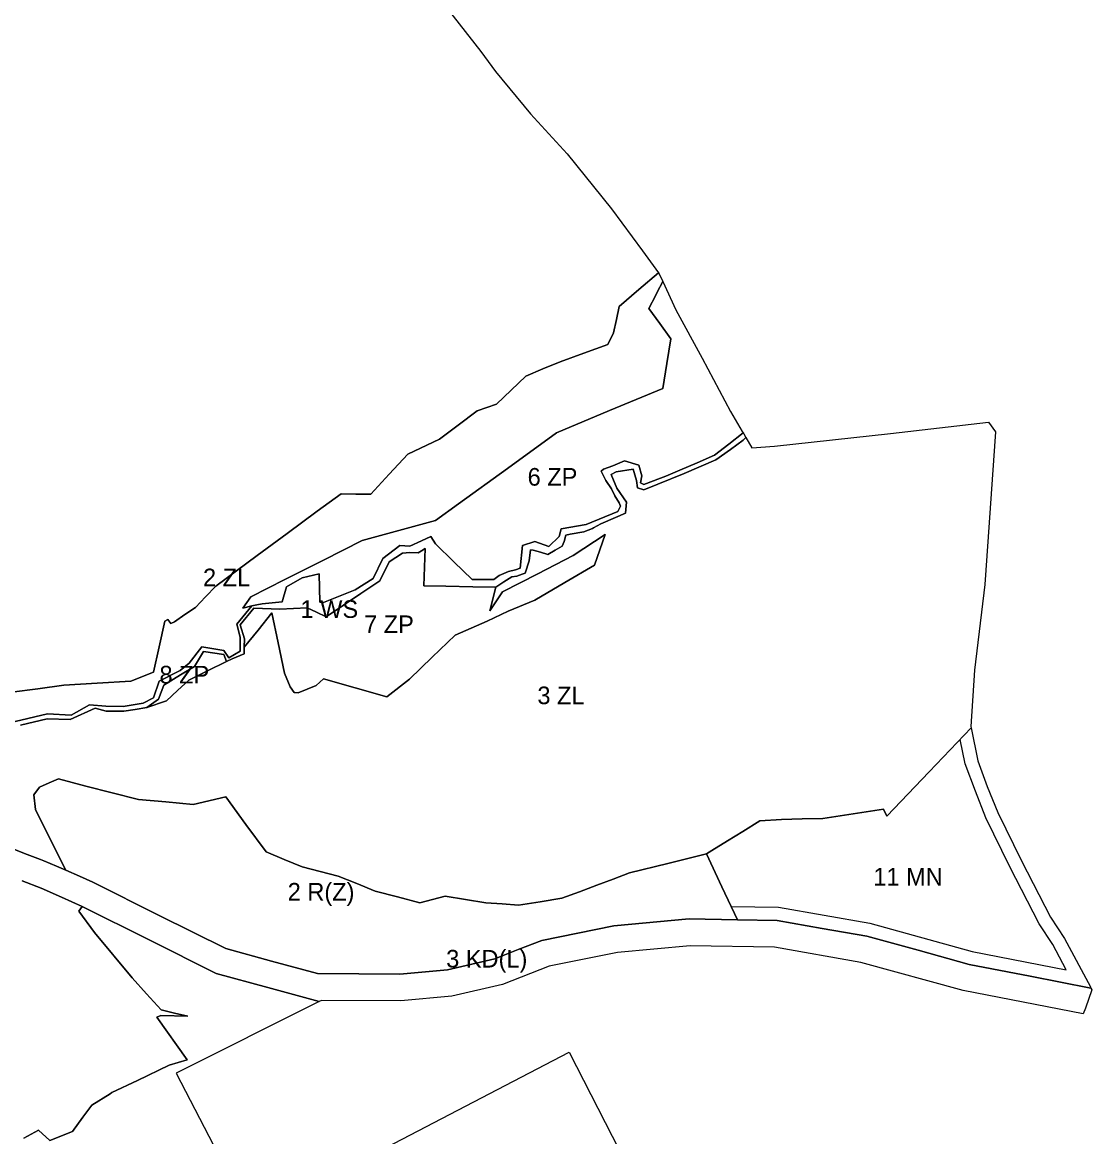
# Model space of a CAD drawing. Extents: x 7423691 to 7425475, y 5552085 to 5554331.
# Drawn here: x 7424989 to 7425475, y 5552921 to 5553427 of the extents above; entities that cross this region are included whole.
import ezdxf

# ---------------------------------------------------------------- set-up
doc = ezdxf.new("R2010")
doc.units = 0
for name, color, linetype in [('linia_zabudowy_nieprzekraczalna', 7, 'Continuous'), ('linie_rozgraniczajace', 7, 'Continuous'), ('oznaczenia_przeznaczen', 7, 'Continuous')]:
    doc.layers.add(name, color=color, linetype=linetype)

msp = doc.modelspace()

# ---------------------------------------------------------------- linework, layer by layer
at = {"layer": 'linia_zabudowy_nieprzekraczalna'}
msp.add_lwpolyline([(7425310.98, 5553025.96), (7425332.48, 5553025.57), (7425373.87, 5553018.32), (7425420.41, 5553005.53), (7425463, 5552997.24), (7425456.94, 5553008.72), (7425450.74, 5553018.12), (7425437.39, 5553044), (7425426.59, 5553066.12), (7425421.88, 5553078.25), (7425417.12, 5553090.67), (7425414.88, 5553101.71)], dxfattribs=at)
at = {"layer": 'linie_rozgraniczajace'}
for points in [[(7425174.89, 5553442.76), (7425197.38, 5553414.04), (7425204.01, 5553404.96), (7425219.92, 5553385.71), (7425236.54, 5553367.58), (7425256.65, 5553342.51), (7425270.66, 5553323.46), (7425277.93, 5553313.56), (7425269.08, 5553305.92), (7425260.22, 5553298.28), (7425258.9, 5553292.27), (7425257.58, 5553286.26), (7425254.94, 5553280.93), (7425244.14, 5553277.04), (7425233.34, 5553273.16), (7425225.57, 5553269.89), (7425217.8, 5553266.62), (7425211.12, 5553260.26), (7425204.44, 5553253.9), (7425195.62, 5553250.91), (7425187.09, 5553244.43), (7425178.55, 5553237.96), (7425164.26, 5553231.17)], [(7424984.37, 5553123.2), (7424996.23, 5553124.78), (7425008.08, 5553126.36), (7425023.27, 5553127.31), (7425038.45, 5553128.25), (7425048.85, 5553132.27), (7425051.36, 5553143.84), (7425053.88, 5553155.41), (7425055.33, 5553156.21), (7425056.71, 5553154.45), (7425058.28, 5553155.19), (7425063.03, 5553158.4), (7425067.78, 5553161.6), (7425072.42, 5553166.44), (7425077.07, 5553171.27), (7425086.44, 5553178.22), (7425095.81, 5553185.18), (7425109.45, 5553195.25), (7425123.08, 5553205.31), (7425128.53, 5553209.28), (7425133.97, 5553213.25), (7425140.68, 5553213.12), (7425147.39, 5553213), (7425155.82, 5553222.08), (7425164.26, 5553231.17), (7425178.55, 5553237.96), (7425187.09, 5553244.43), (7425195.62, 5553250.91), (7425204.44, 5553253.9), (7425211.12, 5553260.26), (7425217.8, 5553266.62), (7425225.57, 5553269.89), (7425233.34, 5553273.16), (7425244.14, 5553277.04), (7425254.94, 5553280.93), (7425257.58, 5553286.26), (7425258.9, 5553292.27), (7425260.22, 5553298.28), (7425269.08, 5553305.92), (7425277.93, 5553313.56), (7425278.32, 5553313.03), (7425279.89, 5553309.63), (7425277.38, 5553304.74), (7425276.73, 5553303.46), (7425273.56, 5553297.29), (7425278.56, 5553290.46), (7425283.57, 5553283.62), (7425281.77, 5553272.35), (7425279.96, 5553261.09), (7425255.82, 5553251), (7425231.68, 5553240.91), (7425209.42, 5553224.79), (7425187.17, 5553208.66), (7425176.76, 5553201.13), (7425160.1, 5553196.59), (7425143.45, 5553192.06), (7425125.91, 5553183.17), (7425108.38, 5553174.29), (7425092.89, 5553166.43), (7425089.31, 5553161.33), (7425093.37, 5553162.39), (7425086.56, 5553154.02), (7425088.12, 5553148.21), (7425088.15, 5553141.83), (7425082.9, 5553138.78), (7425080.71, 5553142.05), (7425070.77, 5553143.82), (7425064.97, 5553136.39), (7425060.96, 5553133.03), (7425051.34, 5553128.27), (7425048.78, 5553120.71), (7425044.11, 5553118.21), (7425035, 5553116.67), (7425027.17, 5553116.83), (7425019.66, 5553117.44), (7425011.4, 5553112.71), (7425000.71, 5553113.41), (7424985.93, 5553109.97)], [(7424988.39, 5553108.24), (7425000.54, 5553111.18), (7425010.99, 5553110.87), (7425022.24, 5553115.95), (7425027.23, 5553114.59), (7425035.27, 5553114.53), (7425040.53, 5553115.41), (7425045.8, 5553116.29), (7425054.68, 5553119.32), (7425059.73, 5553124.03), (7425064.78, 5553128.73), (7425073.35, 5553132.97), (7425081.91, 5553137.2), (7425084.55, 5553138.33), (7425089.94, 5553140.64), (7425089.91, 5553143.58), (7425096.24, 5553151.4), (7425102.56, 5553159.23), (7425105.38, 5553145.55), (7425108.19, 5553131.87), (7425110.76, 5553125.58), (7425112.63, 5553123.06), (7425114.45, 5553122.93), (7425122.55, 5553126.23), (7425125.96, 5553129.2), (7425140.29, 5553125.17), (7425154.62, 5553121.14), (7425164.96, 5553129.05), (7425175.31, 5553139.07), (7425185.67, 5553149.08), (7425200.17, 5553155.46), (7425209.83, 5553159.92), (7425221.85, 5553165.01), (7425235.41, 5553172.91), (7425248.97, 5553180.82), (7425253.74, 5553194.8), (7425239.2, 5553185.23), (7425223.21, 5553176.96), (7425207.23, 5553168.69), (7425201.4, 5553160.13), (7425204.23, 5553170.93), (7425207.84, 5553173.26), (7425211.44, 5553175.59), (7425213.67, 5553175.81), (7425216.08, 5553176.79), (7425217.47, 5553177.18), (7425219.33, 5553182.8), (7425219.86, 5553187.81), (7425221.06, 5553187.67), (7425224.42, 5553186.71), (7425227.79, 5553185.75), (7425231.05, 5553187.62), (7425234.31, 5553189.49), (7425235.16, 5553191.52), (7425235.95, 5553194.4), (7425237.92, 5553194.93), (7425244.14, 5553195.92), (7425247.99, 5553197.55), (7425248.44, 5553197.79), (7425251.86, 5553199.56), (7425258.5, 5553202.49), (7425263, 5553204.41), (7425263.5, 5553209.42), (7425259.04, 5553215.78), (7425256.55, 5553221.93), (7425258.75, 5553223.2), (7425266.52, 5553224.47), (7425268.06, 5553219.27), (7425268.46, 5553216.02), (7425271.27, 5553215.05), (7425277.72, 5553217.62), (7425289.6, 5553222.52), (7425304.07, 5553228.69), (7425310.64, 5553233.41), (7425316.37, 5553237.52), (7425317.62, 5553238.81), (7425320.37, 5553234.15), (7425330.64, 5553234.89), (7425383.28, 5553240.6), (7425427.73, 5553245.73), (7425430.92, 5553241.36), (7425426.1, 5553172.1), (7425421.47, 5553133.23), (7425419.8, 5553107.66), (7425419.94, 5553106.99), (7425400.8, 5553086.99), (7425381.66, 5553066.98), (7425380.1, 5553070.04)], [(7424985.93, 5553109.97), (7425000.71, 5553113.41), (7425011.4, 5553112.71), (7425019.66, 5553117.44), (7425027.17, 5553116.83), (7425035, 5553116.67), (7425044.11, 5553118.21), (7425048.78, 5553120.71), (7425051.34, 5553128.27), (7425060.96, 5553133.03), (7425064.97, 5553136.39), (7425070.77, 5553143.82), (7425080.71, 5553142.05), (7425082.9, 5553138.78), (7425088.15, 5553141.83), (7425088.12, 5553148.21), (7425086.56, 5553154.02), (7425093.37, 5553162.39), (7425095.72, 5553162.82), (7425098.07, 5553163.25), (7425107.12, 5553164.19), (7425109.09, 5553171.06), (7425116.25, 5553175.14), (7425124.05, 5553176.91), (7425124.31, 5553164.11), (7425125.97, 5553163.97), (7425140.27, 5553169.67), (7425148.44, 5553174.82), (7425152.85, 5553183.92), (7425160.63, 5553189.75), (7425165.17, 5553189.47), (7425170.45, 5553191.96), (7425174.64, 5553193.85), (7425176.75, 5553190.53), (7425185.05, 5553182.42), (7425193.35, 5553174.31), (7425203.26, 5553174.42), (7425205.67, 5553176.11), (7425209.97, 5553177.99), (7425213.1, 5553178.7), (7425215.22, 5553179.43), (7425216.2, 5553189.74), (7425221.81, 5553191.55), (7425228.25, 5553189.38), (7425232.93, 5553193.9), (7425233.88, 5553197.36), (7425245.18, 5553199.33), (7425259.6, 5553205.21), (7425260.69, 5553207.59), (7425260.13, 5553209.15), (7425258.25, 5553212.35), (7425256.66, 5553215.52), (7425254.03, 5553219.21), (7425252.03, 5553223.45), (7425252.99, 5553224.39), (7425257.22, 5553225.87), (7425262.59, 5553228.13), (7425269, 5553226.28), (7425270.5, 5553221.4), (7425269.79, 5553218.18), (7425271.4, 5553217.43), (7425278.9, 5553220.26), (7425281.4, 5553221.24), (7425283.48, 5553222.17), (7425287.7, 5553223.94), (7425295.49, 5553227.27), (7425303.45, 5553230.75), (7425309.91, 5553235.84), (7425316.37, 5553240.93), (7425316.67, 5553240.43), (7425317.62, 5553238.81), (7425316.37, 5553237.52), (7425310.64, 5553233.41), (7425304.07, 5553228.69), (7425289.6, 5553222.52), (7425277.72, 5553217.62), (7425271.27, 5553215.05), (7425268.46, 5553216.02), (7425268.06, 5553219.27), (7425266.52, 5553224.47), (7425258.75, 5553223.2), (7425256.55, 5553221.93), (7425259.04, 5553215.78), (7425263.5, 5553209.42), (7425263, 5553204.41), (7425258.5, 5553202.49), (7425251.86, 5553199.56), (7425248.44, 5553197.79), (7425247.99, 5553197.55), (7425244.14, 5553195.92)], [(7425164.26, 5553231.17), (7425155.82, 5553222.08), (7425147.39, 5553213), (7425140.68, 5553213.12), (7425133.97, 5553213.25), (7425128.53, 5553209.28), (7425123.08, 5553205.31), (7425109.45, 5553195.25), (7425095.81, 5553185.18), (7425086.44, 5553178.22), (7425077.07, 5553171.27), (7425072.42, 5553166.44), (7425067.78, 5553161.6), (7425063.03, 5553158.4), (7425058.28, 5553155.19), (7425056.71, 5553154.45), (7425055.33, 5553156.21), (7425053.88, 5553155.41), (7425051.36, 5553143.84), (7425048.85, 5553132.27), (7425038.45, 5553128.25), (7425023.27, 5553127.31), (7425008.08, 5553126.36), (7424996.23, 5553124.78), (7424984.37, 5553123.2)], [(7425244.14, 5553195.92), (7425237.92, 5553194.93), (7425235.95, 5553194.4), (7425235.16, 5553191.52), (7425234.31, 5553189.49), (7425231.05, 5553187.62), (7425227.79, 5553185.75), (7425224.42, 5553186.71), (7425221.06, 5553187.67), (7425219.86, 5553187.81), (7425219.33, 5553182.8), (7425217.47, 5553177.18), (7425216.08, 5553176.79), (7425213.67, 5553175.81), (7425211.44, 5553175.59), (7425207.84, 5553173.26), (7425204.23, 5553170.93), (7425193.78, 5553171.06), (7425181.4, 5553171.32), (7425171.42, 5553171.53), (7425172.15, 5553188.39), (7425170.43, 5553187.39), (7425168.87, 5553186.48), (7425165.13, 5553186.57), (7425161.74, 5553186.29), (7425155.79, 5553182.36), (7425151.58, 5553173.75), (7425142.94, 5553167.94), (7425135.03, 5553162.66), (7425127.12, 5553157.38), (7425122.81, 5553159.47), (7425118.5, 5553161.56), (7425106.06, 5553160.88), (7425094.29, 5553161.31), (7425088.1, 5553153.82), (7425090.16, 5553147.36), (7425089.91, 5553143.59), (7425089.91, 5553143.58), (7425089.94, 5553140.64), (7425084.55, 5553138.33), (7425081.91, 5553137.2), (7425080.72, 5553140.28), (7425071.43, 5553141.66), (7425067.34, 5553134.92), (7425061.07, 5553131.07), (7425053.45, 5553126.4), (7425051.07, 5553119.97), (7425045.8, 5553116.29), (7425040.53, 5553115.41), (7425035.27, 5553114.53), (7425027.23, 5553114.59), (7425022.24, 5553115.95), (7425010.99, 5553110.87), (7425000.54, 5553111.18), (7424988.39, 5553108.24)], [(7425380.1, 5553070.04), (7425374.17, 5553069.15), (7425360.43, 5553067.11), (7425352.62, 5553065.94), (7425343.19, 5553065.66), (7425333.77, 5553065.37), (7425323.95, 5553064.79), (7425316.29, 5553060.05), (7425309.29, 5553055.71), (7425302.28, 5553051.37), (7425299.71, 5553049.79), (7425282.27, 5553045.49), (7425264.83, 5553041.19), (7425257.42, 5553038.42), (7425250.01, 5553035.64), (7425242.1, 5553032.65), (7425234.19, 5553029.66), (7425224.31, 5553028.13), (7425214.43, 5553026.6), (7425207.01, 5553027.13), (7425199.59, 5553027.67), (7425190.38, 5553029.13), (7425181.16, 5553030.58), (7425175.38, 5553029.1), (7425169.6, 5553027.62), (7425159.53, 5553030.28), (7425149.45, 5553032.93), (7425141.04, 5553036.33), (7425132.63, 5553039.73), (7425124.44, 5553041.86), (7425116.25, 5553043.98), (7425108.08, 5553047.33), (7425099.91, 5553050.69), (7425090.73, 5553063.17), (7425081.55, 5553075.65), (7425066.77, 5553072.25), (7425054.37, 5553073.38), (7425041.97, 5553074.51), (7425030.06, 5553077.54), (7425018.14, 5553080.57), (7425005.69, 5553083.89), (7425001.36, 5553082), (7424997.02, 5553080.11), (7424994.52, 5553076.63), (7424995.15, 5553069.94), (7425002.1, 5553056.18), (7425009.04, 5553042.42), (7425004.82, 5553044.3), (7424998.98, 5553046.7), (7424997.44, 5553047.3), (7424991.49, 5553049.58), (7424984.92, 5553052.11)], [(7424984.92, 5553052.11), (7424991.49, 5553049.58), (7424997.44, 5553047.3), (7424998.98, 5553046.7), (7425004.82, 5553044.3), (7425009.04, 5553042.42), (7425015.15, 5553039.68), (7425021.25, 5553036.95), (7425051.39, 5553021.89), (7425081.54, 5553006.84), (7425102.39, 5553001.17), (7425123.24, 5552995.5), (7425141.91, 5552995.38), (7425160.59, 5552995.27), (7425182.3, 5552997.2), (7425203.66, 5553002.25), (7425214.32, 5553006.37), (7425224.98, 5553010.5), (7425241.34, 5553013.83), (7425257.7, 5553017.16), (7425291.97, 5553020.3), (7425313.84, 5553019.91), (7425331.91, 5553019.58), (7425352.23, 5553016.02), (7425372.55, 5553012.46), (7425395.8, 5553006.07), (7425419.04, 5552999.68), (7425446.66, 5552994.31), (7425474.29, 5552988.93), (7425474.63, 5552988.05), (7425471.74, 5552979.82), (7425470.77, 5552977.23), (7425416.24, 5552987.84), (7425369.87, 5553000.59), (7425330.7, 5553007.45), (7425292.36, 5553008.14), (7425259.4, 5553005.12), (7425228.31, 5552998.79), (7425207.16, 5552990.61), (7425184.17, 5552985.18), (7425161.03, 5552983.11), (7425125.03, 5552983.34), (7425124.05, 5552982.85), (7425100.64, 5552989.21), (7425077.24, 5552995.57), (7425046.79, 5553010.78), (7425016.35, 5553026), (7425007.05, 5553030.16), (7424997.75, 5553034.32), (7424989.1, 5553037.64)], [(7424989.1, 5553037.64), (7424997.75, 5553034.32), (7425007.05, 5553030.16), (7425016.35, 5553026), (7425014.91, 5553023.77), (7425022.01, 5553014.15), (7425039.11, 5552993.64), (7425045.66, 5552986.35), (7425052.21, 5552979.06), (7425058.27, 5552977.58), (7425064.33, 5552976.1), (7425052.17, 5552976.42), (7425050.24, 5552975.78), (7425064, 5552956.38), (7425055.95, 5552953.87), (7425041.5, 5552946.99), (7425029.93, 5552941.48), (7425029.07, 5552940.94), (7425020.72, 5552935.8), (7425016.76, 5552930.36), (7425011.96, 5552923.77), (7425001.77, 5552919.8), (7424996.57, 5552924.37), (7424989.86, 5552920.81)], [(7424989.86, 5552920.81), (7424996.57, 5552924.37), (7425001.77, 5552919.8), (7425011.96, 5552923.77), (7425016.76, 5552930.36), (7425020.72, 5552935.8), (7425029.07, 5552940.94), (7425029.93, 5552941.48), (7425041.5, 5552946.99), (7425055.95, 5552953.87), (7425064, 5552956.38), (7425050.24, 5552975.78), (7425052.17, 5552976.42), (7425064.33, 5552976.1), (7425058.27, 5552977.58), (7425052.21, 5552979.06), (7425045.66, 5552986.35), (7425039.11, 5552993.64), (7425022.01, 5553014.15), (7425014.91, 5553023.77), (7425016.35, 5553026), (7425046.79, 5553010.78), (7425077.24, 5552995.57), (7425100.64, 5552989.21), (7425124.05, 5552982.85), (7425059.04, 5552950.27), (7425093.05, 5552884.67), (7425237.44, 5552959.76), (7425273.37, 5552889.73)]]:
    msp.add_lwpolyline(points, dxfattribs=at)
for points in [[(7425089.31, 5553161.33), (7425092.89, 5553166.43), (7425108.38, 5553174.29), (7425125.91, 5553183.17), (7425143.45, 5553192.06), (7425160.1, 5553196.59), (7425176.76, 5553201.13), (7425187.17, 5553208.66), (7425209.42, 5553224.79), (7425231.68, 5553240.91), (7425255.82, 5553251), (7425279.96, 5553261.09), (7425281.77, 5553272.35), (7425283.57, 5553283.62), (7425278.56, 5553290.46), (7425273.56, 5553297.29), (7425276.73, 5553303.46), (7425277.38, 5553304.74), (7425279.89, 5553309.63), (7425285.89, 5553296.68), (7425297.84, 5553274.81), (7425310.71, 5553250.62), (7425316.01, 5553241.54), (7425316.37, 5553240.93), (7425309.91, 5553235.84), (7425303.45, 5553230.75), (7425295.49, 5553227.27), (7425287.7, 5553223.94), (7425283.48, 5553222.17), (7425281.4, 5553221.24), (7425278.9, 5553220.26), (7425271.4, 5553217.43), (7425269.79, 5553218.18), (7425270.5, 5553221.4), (7425269, 5553226.28), (7425262.59, 5553228.13), (7425257.22, 5553225.87), (7425252.99, 5553224.39), (7425252.03, 5553223.45), (7425254.03, 5553219.21), (7425256.66, 5553215.52), (7425258.25, 5553212.35), (7425260.13, 5553209.15), (7425260.69, 5553207.59), (7425259.6, 5553205.21), (7425245.18, 5553199.33), (7425233.88, 5553197.36), (7425232.93, 5553193.9), (7425228.25, 5553189.38), (7425221.81, 5553191.55), (7425216.2, 5553189.74), (7425215.22, 5553179.43), (7425213.1, 5553178.7), (7425209.97, 5553177.99), (7425205.67, 5553176.11), (7425203.26, 5553174.42), (7425193.35, 5553174.31), (7425185.05, 5553182.42), (7425176.75, 5553190.53), (7425174.64, 5553193.85), (7425170.45, 5553191.96), (7425165.17, 5553189.47), (7425160.63, 5553189.75), (7425152.85, 5553183.92), (7425148.44, 5553174.82), (7425140.27, 5553169.67), (7425125.97, 5553163.97), (7425124.31, 5553164.11), (7425124.05, 5553176.91), (7425116.25, 5553175.14), (7425109.09, 5553171.06), (7425107.12, 5553164.19), (7425098.07, 5553163.25), (7425095.72, 5553162.82), (7425093.37, 5553162.39)], [(7425088.1, 5553153.82), (7425094.29, 5553161.31), (7425106.06, 5553160.88), (7425118.5, 5553161.56), (7425122.81, 5553159.47), (7425127.12, 5553157.38), (7425135.03, 5553162.66), (7425142.94, 5553167.94), (7425151.58, 5553173.75), (7425155.79, 5553182.36), (7425161.74, 5553186.29), (7425165.13, 5553186.57), (7425168.87, 5553186.48), (7425170.43, 5553187.39), (7425172.15, 5553188.39), (7425171.42, 5553171.53), (7425181.4, 5553171.32), (7425193.78, 5553171.06), (7425204.23, 5553170.93), (7425201.4, 5553160.13), (7425207.23, 5553168.69), (7425223.21, 5553176.96), (7425239.2, 5553185.23), (7425253.74, 5553194.8), (7425248.97, 5553180.82), (7425235.41, 5553172.91), (7425221.85, 5553165.01), (7425209.83, 5553159.92), (7425200.17, 5553155.46), (7425185.67, 5553149.08), (7425175.31, 5553139.07), (7425164.96, 5553129.05), (7425154.62, 5553121.14), (7425140.29, 5553125.17), (7425125.96, 5553129.2), (7425122.55, 5553126.23), (7425114.45, 5553122.93), (7425112.63, 5553123.06), (7425110.76, 5553125.58), (7425108.19, 5553131.87), (7425105.38, 5553145.55), (7425102.56, 5553159.23), (7425096.24, 5553151.4), (7425089.91, 5553143.58), (7425089.91, 5553143.59), (7425090.16, 5553147.36)], [(7425045.8, 5553116.29), (7425051.07, 5553119.97), (7425053.45, 5553126.4), (7425061.07, 5553131.07), (7425067.34, 5553134.92), (7425071.43, 5553141.66), (7425080.72, 5553140.28), (7425081.91, 5553137.2), (7425073.35, 5553132.97), (7425064.78, 5553128.73), (7425059.73, 5553124.03), (7425054.68, 5553119.32)], [(7425299.71, 5553049.79), (7425302.28, 5553051.37), (7425309.29, 5553055.71), (7425316.29, 5553060.05), (7425323.95, 5553064.79), (7425333.77, 5553065.37), (7425343.19, 5553065.66), (7425352.62, 5553065.94), (7425360.43, 5553067.11), (7425374.17, 5553069.15), (7425380.1, 5553070.04), (7425381.66, 5553066.98), (7425400.8, 5553086.99), (7425419.94, 5553106.99), (7425422.98, 5553091.99), (7425427.21, 5553080.45), (7425432.09, 5553068.53), (7425442.75, 5553046.69), (7425455.92, 5553021.16), (7425462.35, 5553011.41), (7425474.06, 5552989.52), (7425474.29, 5552988.93), (7425446.66, 5552994.31), (7425419.04, 5552999.68), (7425395.8, 5553006.07), (7425372.55, 5553012.46), (7425352.23, 5553016.02), (7425331.91, 5553019.58), (7425313.84, 5553019.91), (7425306.78, 5553034.85)], [(7424994.52, 5553076.63), (7424997.02, 5553080.11), (7425001.36, 5553082), (7425005.69, 5553083.89), (7425018.14, 5553080.57), (7425030.06, 5553077.54), (7425041.97, 5553074.51), (7425054.37, 5553073.38), (7425066.77, 5553072.25), (7425081.55, 5553075.65), (7425090.73, 5553063.17), (7425099.91, 5553050.69), (7425108.08, 5553047.33), (7425116.25, 5553043.98), (7425124.44, 5553041.86), (7425132.63, 5553039.73), (7425141.04, 5553036.33), (7425149.45, 5553032.93), (7425159.53, 5553030.28), (7425169.6, 5553027.62), (7425175.38, 5553029.1), (7425181.16, 5553030.58), (7425190.38, 5553029.13), (7425199.59, 5553027.67), (7425207.01, 5553027.13), (7425214.43, 5553026.6), (7425224.31, 5553028.13), (7425234.19, 5553029.66), (7425242.1, 5553032.65), (7425250.01, 5553035.64), (7425257.42, 5553038.42), (7425264.83, 5553041.19), (7425282.27, 5553045.49), (7425299.71, 5553049.79), (7425306.78, 5553034.85), (7425313.84, 5553019.91), (7425291.97, 5553020.3), (7425257.7, 5553017.16), (7425241.34, 5553013.83), (7425224.98, 5553010.5), (7425214.32, 5553006.37), (7425203.66, 5553002.25), (7425182.3, 5552997.2), (7425160.59, 5552995.27), (7425141.91, 5552995.38), (7425123.24, 5552995.5), (7425102.39, 5553001.17), (7425081.54, 5553006.84), (7425051.39, 5553021.89), (7425021.25, 5553036.95), (7425015.15, 5553039.68), (7425009.04, 5553042.42), (7425002.1, 5553056.18), (7424995.15, 5553069.94)]]:
    msp.add_lwpolyline(points, close=True, dxfattribs=at)

# ---------------------------------------------------------------- texts
at = {"layer": 'oznaczenia_przeznaczen'}
for s, p in [('6 ZP', (7425218.59, 5553216.94)), ('2 ZL', (7425071.26, 5553171.29)), ('1 WS', (7425115.52, 5553156.94)), ('7 ZP', (7425144.35, 5553150.02)), ('8 ZP', (7425051.49, 5553127.16)), ('3 ZL', (7425223.03, 5553117.76)), ('11 MN', (7425375.48, 5553035.46)), ('2 R(Z)', (7425109.69, 5553028.64)), ('3 KD(L)', (7425181.63, 5552998.25))]:
    msp.add_text(s, height=8, dxfattribs=at).set_placement(p)

doc.saveas('drawing.dxf')
